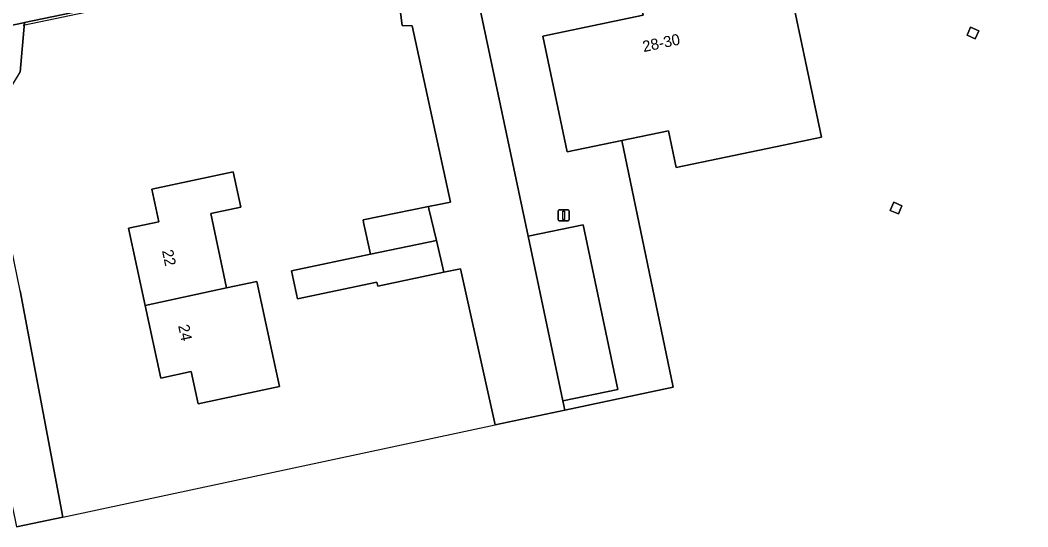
# Model space of a CAD drawing. Extents: x 164494 to 166241, y 382475 to 384495.
# Drawn here: x 164931.2 to 165022, y 384284.2 to 384329.9 of the extents above; entities that cross this region are included whole.
import ezdxf

# ---------------------------------------------------------------- set-up
doc = ezdxf.new("R2010")
doc.units = 0
for name, color, linetype in [('IMGEO_Erf', 7, 'Continuous'), ('IMGEO_Groenvoorziening', 7, 'Continuous'), ('IMGEO_Hek', 7, 'Continuous'), ('IMGEO_Hoogspanningsmast', 7, 'Continuous'), ('IMGEO_Lichtmast', 7, 'Continuous'), ('IMGEO_Pand', 7, 'Continuous'), ('IMGEO_Pand_nummerreeks', 7, 'Continuous'), ('IMGEO_Parkeervlak_open', 7, 'Continuous'), ('IMGEO_Rijbaan_lokaal_open', 7, 'Continuous'), ('IMGEO_Voetpad_open', 7, 'Continuous')]:
    doc.layers.add(name, color=color, linetype=linetype)

msp = doc.modelspace()

# ---------------------------------------------------------------- linework, layer by layer
at = {"layer": 'IMGEO_Erf'}
for points in [[(164960.93, 384335.824), (164931.595, 384329.704), (164931.189, 384325.235)], [(165000.234, 384334.604), (165003.425, 384319.356), (165000, 384318.639), (164990.338, 384316.617), (164989.641, 384319.943), (164985.443, 384319.065), (164990.062, 384296.82), (164980.294, 384294.743), (164974.03, 384293.405), (164970.898, 384307.493), (164969.392, 384307.192), (164963.428, 384305.923), (164963.349, 384306.281), (164956.184, 384304.779), (164955.655, 384307.305), (164962.793, 384308.801), (164962.158, 384311.679), (164962.107, 384311.911), (164967.996, 384313.104), (164968.93, 384313.293), (164969.978, 384313.506), (164966.532, 384329.404), (164965.642, 384329.426), (164965.275, 384332.269)], [(164931.192, 384305.516), (164935.029, 384285.096), (164930.87, 384284.21)]]:
    msp.add_lwpolyline(points, dxfattribs=at)
for points in [[(165016.562, 384328.557), (165016.73, 384328.939), (165016.883, 384329.29), (165017.616, 384328.969), (165017.295, 384328.236)], [(164947.236, 384295.294), (164946.605, 384298.226), (164943.867, 384297.637), (164942.459, 384304.183), (164940.961, 384311.148), (164943.699, 384311.737), (164943.069, 384314.67), (164950.412, 384316.25), (164951.1, 384313.054), (164948.373, 384312.468), (164949.804, 384305.763), (164952.532, 384306.349), (164953.886, 384300.05), (164954.569, 384296.872)], [(165009.635, 384312.76), (165009.956, 384313.493), (165010.689, 384313.172), (165010.368, 384312.439)]]:
    msp.add_lwpolyline(points, close=True, dxfattribs=at)
at = {"layer": 'IMGEO_Groenvoorziening'}
msp.add_lwpolyline([(164985.443, 384319.065), (164980.499, 384318.03), (164978.312, 384328.483), (164987.376, 384330.38), (164987.069, 384331.849), (164987.642, 384331.969), (164985.728, 384340.992), (164976.791, 384339.123), (164976.708, 384339.106), (164972.661, 384333.951), (164973.308, 384330.982), (164972.656, 384330.873), (164976.99, 384310.432), (164981.938, 384311.469), (164985.086, 384296.596), (164980.116, 384295.575), (164980.294, 384294.743), (164990.062, 384296.82)], close=True, dxfattribs=at)
at = {"layer": 'IMGEO_Hek'}
for points in [[(164961.143, 384335.672), (164931.464, 384329.449)], [(164980.294, 384294.743), (164990.062, 384296.82), (164985.443, 384319.065)], [(164935.029, 384285.096), (164974.03, 384293.405)]]:
    msp.add_lwpolyline(points, dxfattribs=at)
at = {"layer": 'IMGEO_Hoogspanningsmast'}
for points in [[(165016.883, 384329.29), (165016.73, 384328.939), (165016.562, 384328.557), (165017.295, 384328.236), (165017.616, 384328.969)], [(165009.956, 384313.493), (165009.635, 384312.76), (165010.368, 384312.439), (165010.689, 384313.172)]]:
    msp.add_lwpolyline(points, close=True, dxfattribs=at)
at = {"layer": 'IMGEO_Lichtmast'}
for p, q in [((164979.696, 384311.906), (164979.696, 384312.706)), ((164979.696, 384312.706), (164979.696, 384311.906)), ((164979.796, 384312.806), (164980.586, 384312.806)), ((164980.586, 384312.806), (164979.796, 384312.806)), ((164980.686, 384312.706), (164980.686, 384311.906)), ((164980.686, 384311.906), (164980.686, 384312.706)), ((164980.586, 384311.806), (164979.796, 384311.806)), ((164979.796, 384311.806), (164980.586, 384311.806))]:
    msp.add_line(p, q, dxfattribs=at)
msp.add_lwpolyline([(164980.116, 384312.681), (164980.266, 384312.681), (164980.266, 384311.931), (164980.116, 384311.931), (164980.116, 384312.681)], dxfattribs=at)
for centre, start, end in [((164979.796, 384312.706), 90, 180), ((164979.796, 384312.706), 90, 180), ((164980.586, 384312.706), 0, 90), ((164980.586, 384312.706), 360, 90), ((164979.796, 384311.906), 180, 270), ((164979.796, 384311.906), 180, 270), ((164980.586, 384311.906), 270, 0), ((164980.586, 384311.906), 270, 0)]:
    msp.add_arc(centre, 0.1, start, end, dxfattribs=at)
at = {"layer": 'IMGEO_Pand'}
for points in [[(164988.553, 384332.16), (164987.642, 384331.969), (164987.069, 384331.849), (164987.376, 384330.38), (164978.312, 384328.483), (164980.499, 384318.03), (164985.443, 384319.065), (164989.641, 384319.943), (164990.338, 384316.617), (165000, 384318.639), (165003.425, 384319.356), (165000.234, 384334.604), (165000, 384334.555)], [(164942.459, 384304.183), (164949.804, 384305.763), (164948.373, 384312.468), (164951.1, 384313.054), (164950.412, 384316.25), (164943.069, 384314.67), (164943.699, 384311.737), (164940.961, 384311.148)], [(164968.719, 384310.043), (164968.046, 384312.894), (164967.996, 384313.104), (164962.107, 384311.911), (164962.158, 384311.679), (164962.793, 384308.801)], [(164968.719, 384310.043), (164962.793, 384308.801), (164955.655, 384307.305), (164956.184, 384304.779), (164963.349, 384306.281), (164963.428, 384305.923), (164969.392, 384307.192)], [(164942.459, 384304.183), (164943.867, 384297.637), (164946.605, 384298.226), (164947.236, 384295.294), (164954.569, 384296.872), (164953.886, 384300.05), (164952.532, 384306.349), (164949.804, 384305.763)]]:
    msp.add_lwpolyline(points, close=True, dxfattribs=at)
at = {"layer": 'IMGEO_Parkeervlak_open'}
msp.add_lwpolyline([(164976.99, 384310.432), (164980.116, 384295.575), (164985.086, 384296.596), (164981.938, 384311.469)], close=True, dxfattribs=at)
at = {"layer": 'IMGEO_Rijbaan_lokaal_open'}
for points in [[(164972.656, 384330.873), (164973.308, 384330.982), (164972.661, 384333.951), (164976.708, 384339.106), (164961.279, 384335.897), (164960.93, 384335.824), (164965.275, 384332.269), (164965.642, 384329.426), (164966.532, 384329.404), (164969.978, 384313.506), (164968.93, 384313.293), (164967.996, 384313.104), (164968.046, 384312.894), (164968.719, 384310.043), (164969.392, 384307.192), (164970.898, 384307.493), (164974.03, 384293.405), (164980.294, 384294.743), (164980.116, 384295.575), (164976.99, 384310.432)], [(164928.461, 384318.744), (164929.571, 384322.569), (164931.189, 384325.235), (164931.595, 384329.704), (164931.494, 384329.683), (164913.849, 384326.017), (164913.321, 384325.907), (164913.602, 384324.675), (164914.593, 384324.849), (164914.805, 384323.848), (164923.539, 384319.297), (164928.077, 384297.39), (164930.735, 384284.803), (164930.87, 384284.21), (164935.029, 384285.096), (164931.192, 384305.516)]]:
    msp.add_lwpolyline(points, close=True, dxfattribs=at)
at = {"layer": 'IMGEO_Voetpad_open'}
msp.add_lwpolyline([(164913.849, 384326.017), (164931.494, 384329.683), (164931.595, 384329.704), (164960.93, 384335.824), (164961.279, 384335.897), (164976.708, 384339.106), (164976.791, 384339.123), (164985.728, 384340.992), (164986.639, 384341.182), (164997.097, 384343.369), (164998.345, 384343.632), (165002.371, 384344.482), (165003.041, 384344.622), (165006.564, 384345.357), (165007.446, 384345.541), (165052.6, 384354.959), (165101.82, 384365.255), (165121.469, 384369.317)], dxfattribs=at)

# ---------------------------------------------------------------- texts
at = {"layer": 'IMGEO_Pand_nummerreeks'}
for s, rotation, p in [('28-30', 11.82078, (164987.414, 384327.037)), ('22', 282.13848, (164943.977, 384309.111)), ('24', 282.13848, (164945.431, 384302.353))]:
    msp.add_text(s, height=1, rotation=rotation, dxfattribs=at).set_placement(p)

doc.saveas('drawing.dxf')
